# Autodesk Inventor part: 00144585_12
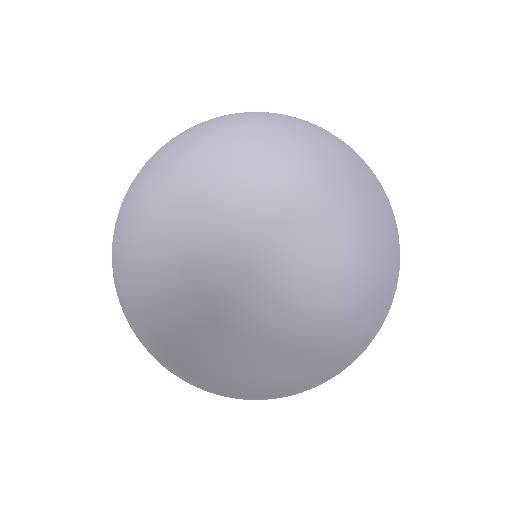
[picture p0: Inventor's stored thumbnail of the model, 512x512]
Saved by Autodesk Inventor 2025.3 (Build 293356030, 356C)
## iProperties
Created: 2021-02
Part Number: 00144585_12
Material: Generico
Document SubType Name: Modeling
Designer: R5800u
Density: 1 g/cm^3
Appearance: Default
Author: TraceParts
Sending System: SolidWorks 2021
Last Author: Albert
Last Saved: 2021-07-28
IsFastener: 1
TYPE: CATASM
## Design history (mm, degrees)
feature "Imported1"
node "Solido1"
